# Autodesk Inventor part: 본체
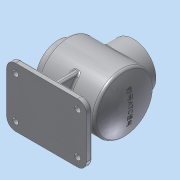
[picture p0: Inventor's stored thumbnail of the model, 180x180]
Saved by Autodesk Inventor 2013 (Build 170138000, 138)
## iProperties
Created: 2016-09
Part Number: 본체
Material: 알루미늄 6061
Document SubType Name: Modeling
Designer: Administrator
Density: 2.71 g/cm^3
Mass: 972.435 g
Surface Area: 1283.07 cm^2
Volume: 358.832 cm^3
Author: Administrator
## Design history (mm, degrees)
sketch "스케치1"
  geometry: L1 (-61, 0)-(61, 0); L2 (-61, 0)-(-61, 38); L3 (-61, 38)-(-49, 38); L4 (-49, 38)-(-49, 50); L5 (-49, 50)-(49.562, 50); A1 r 115 centre (-54, 0) between (61, 0) and (49.562, 50); 2 further points
  constraints: 10 end point, 2 parallel, 2 point on circle, 1 centre point, 1 coincident, 1 horizontal, 1 midpoint, 1 perpendicular, 1 point on line, 1 vertical
  dimensions: "d0" = 122 distance of L1.start L1.end; "d3" = 100 diameter of L5 L1; "d4" = 76 diameter of L3 L1; "d5" = 115 radius of A1; "d93" = 110 distance from line of L1.end L4
revolve "회전1" sketch "스케치1" stored, may be unused: angle "d6" = 90 deg
sketch "스케치2"
  geometry: L1 (61, 38)-(61, -38) reference; L2 (49, 50)-(-49.562, 50) reference; L3 (61, 0)-(-61, 0); L4 (61, 27)-(46, 27); L5 (46, 27)-(46, 47); L6 (46, 47)-(-47.661, 47); L7 (49, 50)-(49, -50) reference; L8 (61, 27)-(61, 0); A1 r 115 centre (54, 0) between (-49.562, 50) and (-49.562, -50) reference; A2 r 112 centre (54, 0) between (-47.661, 47) and (-58, 0); 1 further point
  constraints: 10 end point, 3 point on circle, 2 parallel, 2 perpendicular, 2 point on line, 1 centre point, 1 midpoint
  dimensions: "d8" = 3 radial gap between concentric circles of A1 A2; "d9" = 3 distance between parallel lines of L2 L6; "d10" = 3 distance between parallel lines of L7 L5; "d11" = 54 diameter of L4 L3
revolve "회전2" sketch "스케치2" stored, may be unused: angle "d12" = 90 deg
fillet "모깎기1" dims "d13" = 5
fillet "모깎기2" dims "d14" = 3
fillet "모깎기3" dims "d15" = 2
sketch "스케치3"
  geometry: C1 r 27 at (0, 0) reference; 1 further point
  constraints: 1 vertical alignment
  dimensions: "d16" = 32.5 distance of C1.centre point (0, 32.5)
hole "구멍1" sketch "스케치3" at (0, 32.5) diameter "d17" = 3.242; stored, may be unused: countersink angle "d21" = 90 deg, drill point angle "d23" = 118 deg; dims "d18" = 8, "d19" = 4, "d20" = 2, "d22" = 10
node "작업 평면1"
sketch "스케치4"
  geometry: L1 (49, 45)-(49, -45) reference; C1 r 38 at (-1, 0); 1 further point
  constraints: 1 centre point, 1 horizontal alignment
  dimensions: "d28" = 76 diameter of C1; "d30" = 50 distance from line of C1.centre L1
extrude "돌출1" join sketch "스케치4" stored distance "d31" = 10; taper "d32" = 0 deg
sketch "스케치5"
  geometry: C1 r 38 at (0, 0) reference; C2 r 27 at (0, 0); 1 further point
  constraints: 1 centre point, 1 coincident
  dimensions: "d33" = 54 diameter of C2
extrude "돌출2" cut sketch "스케치5" stored distance "d35" = 10; taper "d36" = 0 deg
sketch "스케치6"
  geometry: C1 r 27 at (0, 0) reference; 2 further points
  constraints: 1 vertical alignment
  dimensions: "d37" = 32.5 distance of C1.centre point (0, 32.5)
hole "구멍2" sketch "스케치6" at (0, 32.5) diameter "d38" = 3.242; stored, may be unused: countersink angle "d42" = 90 deg, drill point angle "d44" = 118 deg; dims "d39" = 8, "d40" = 4, "d41" = 2, "d43" = 10
fillet "모깎기4" dims "d48" = 3
node "작업 평면2"
sketch "스케치7"
  geometry: L1 (-66.5, 50)-(68.5, 50); L2 (68.5, 50)-(68.5, -50); L3 (68.5, -50)-(-66.5, -50); L4 (-66.5, -50)-(-66.5, 50); C1 r 38 at (1, 0) reference; 3 further points
  constraints: 8 end point, 2 midpoint, 2 parallel, 1 horizontal, 1 horizontal alignment, 1 perpendicular, 1 vertical alignment
  dimensions: "d50" = 135 distance of L1.start L1.end; "d52" = 100 distance of L1.end L2.end
extrude "돌출3" join sketch "스케치7" distance "d53" = 10; taper "d54" = 0 deg
fillet "모깎기7" dims "d81" = 15
fillet "모깎기8" dims "d82" = 3
sketch "스케치11"
  geometry: C1 r 5 at (-51.5, 35); C2 r 5 at (53.5, 35); C3 r 5 at (53.5, -35); C4 r 5 at (-51.5, -35); A1 r 15 centre (53.5, -35) between (53.5, -50) and (68.5, -35) reference; A2 r 15 centre (53.5, 35) between (68.5, 35) and (53.5, 50) reference; A3 r 15 centre (-51.5, 35) between (-51.5, 50) and (-66.5, 35) reference; A4 r 15 centre (-51.5, -35) between (-66.5, -35) and (-51.5, -50) reference; 1 further point
  constraints: 4 centre point, 4 coincident, 3 equal radius
  dimensions: "d83" = 10 diameter of C1
extrude "돌출5" cut sketch "스케치11" distance "d85" = 10; taper "d86" = 0 deg
node "작업 평면3"
sketch "스케치12"
  geometry: 2 further points
  constraints: 1 coincident, 1 other
feature "엠보싱1" sketch "스케치12" dims "d0" = 122, "d88" = 0.5, "d89" = 0
chamfer "모따기1" distance "d90" = 1; stored, may be unused: second distance "d91" = 2, angle "d92" = 45 deg
node "작업 평면4"
sketch "스케치13"
  geometry: L1 (0, 10)-(70, 10) reference; L2 (-5, 10)-(5, 10) reference; L3 (70, 10)-(82, 10) reference; L4 (-12, 10)-(0, 10) reference; L5 (-5, 52)-(-5, 10); L6 (75, 52)-(75, 10); A1 r 50 centre (35, 82) between (-5, 52) and (75, 52) reference; 1 further point
  constraints: 4 end point, 2 perpendicular, 2 point on circle, 2 point on line
  dimensions: "d95" = 40 distance from line of L5 point (35, 82); "d96" = 40 distance from line of L6 point (35, 82)
extrude "돌출6" join sketch "스케치13" stored distance "d97" = 10; taper "d98" = 0 deg
sketch "스케치14"
  geometry: L1 (-44, -50)-(46.374, -50) reference; L2 (-4, -30)-(-4, -72) reference; L3 (-51.5, -72)-(53.5, -72) reference; L4 (29, 65)-(-27, 65) reference; L5 (1, 65)-(1, -8.254); L6 (-37.075, -50)-(-39, -72); 1 further point
  constraints: 4 end point, 2 point on line, 1 midpoint, 1 perpendicular
  dimensions: "d100" = 95 deg angle of L6 L3; "d120" = 40 distance from line of L5 L6.end
feature "리브3" sketch "스케치14" dims "d101" = 1, "d102" = 10, "d103" = 0, "d104" = 0, "d105" = 1, "d106" = 1
sketch "스케치15"
  geometry: L1 (-51.5, -72)-(53.5, -72) reference; L2 (-44, -50)-(46.374, -50) reference; L3 (29, 65)-(-27, 65) reference; L4 (1, 65)-(1, -19.091); L5 (39.075, -50)-(41, -72); 1 further point
  constraints: 4 end point, 2 point on line, 1 midpoint, 1 perpendicular
  dimensions: "d107" = 40 distance from line of L4 L5.end; "d109" = 95 deg angle of L5 L1
feature "리브4" sketch "스케치15" dims "d111" = 1, "d112" = 10, "d113" = 0, "d114" = 0, "d115" = 1, "d116" = 1
fillet "모깎기9" dims "d117" = 3
fillet "모깎기10" dims "d118" = 3
fillet "모깎기11" dims "d119" = 3
node "솔리드1"
pattern_circular "원형 패턴1" dims angle "d25" = 360 deg
pattern_circular "원형 패턴2" dims angle "d46" = 360 deg
other parameters: "d27" = 65, "d49" = -82, "d87" = 123.75, "d94" = -67.5
